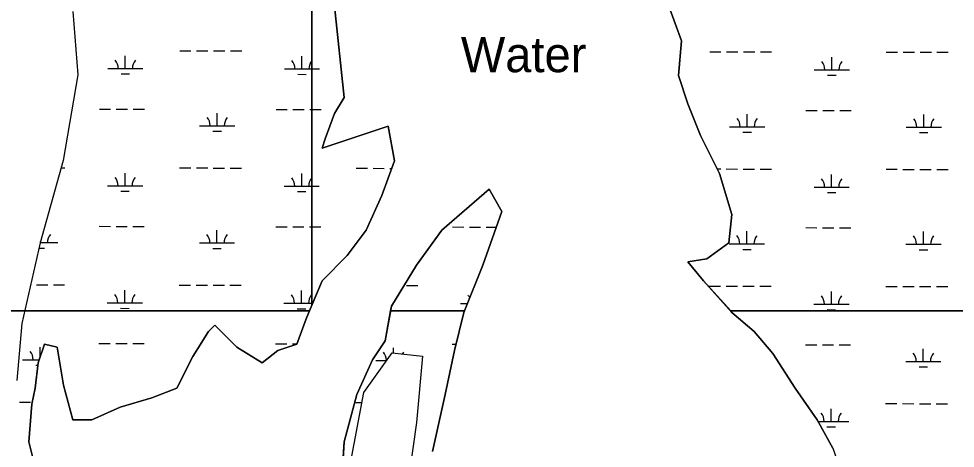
# Model space of a CAD drawing. Extents: x 3192952 to 3230831, y 849296 to 874698.
# Drawn here: x 3197892 to 3200553, y 858613 to 859832 of the extents above; entities that cross this region are included whole.
import ezdxf

# ---------------------------------------------------------------- set-up
doc = ezdxf.new("R2010")
doc.units = 0
for name, color, linetype in [('V-RIVR-IDEN', 7, 'Continuous'), ('V-SITE-VEGE', 7, 'Continuous'), ('V-TOPO-SHOR', 7, 'Continuous'), ('V-WETL-SWMP', 7, 'Continuous')]:
    doc.layers.add(name, color=color, linetype=linetype)

msp = doc.modelspace()

# ---------------------------------------------------------------- linework, layer by layer
at = {"layer": 'V-SITE-VEGE'}
for p, q in [((3198816.5, 859607.9), (3198789.6, 859868)), ((3199739.4, 859868), (3199775.3, 859769.3)), ((3199775.3, 859769.3), (3199766.3, 859670.7)), ((3199766.3, 859670.7), (3199793.2, 859590)), ((3198789.6, 859563.1), (3198816.5, 859607.9)), ((3199793.2, 859590), (3199829, 859500.3)), ((3198762.7, 859491.3), (3198789.6, 859563.1)), ((3198941.9, 859527.2), (3198753.8, 859464.4)), ((3198959.9, 859428.6), (3198941.9, 859527.2)), ((3198753.8, 859464.4), (3198762.7, 859491.3)), ((3199829, 859500.3), (3199882.8, 859392.7)), ((3198924, 859329.9), (3198959.9, 859428.6)), ((3199882.8, 859392.7), (3199918.6, 859276.1)), ((3198879.2, 859231.3), (3198924, 859329.9)), ((3199918.6, 859276.1), (3199909.7, 859195.4)), ((3198825.5, 859159.5), (3198879.2, 859231.3)), ((3199909.7, 859195.4), (3199847, 859150.6)), ((3198753.8, 859087.8), (3198825.5, 859159.5)), ((3199847, 859150.6), (3199793.2, 859141.6)), ((3199793.2, 859141.6), (3199838, 859087.8)), ((3198718.1, 859002.2), (3198753.8, 859087.8)), ((3199838, 859087.8), (3199915, 859002.2)), ((3197154.3, 859002.2), (3198718.1, 859002.2)), ((3198718.1, 859002.2), (3197154.3, 859002.2)), ((3198682.1, 858908.4), (3198709, 858980.2)), ((3198709, 858980.2), (3198718.1, 859002.2)), ((3198948.4, 859002.2), (3198933, 858917.4)), ((3199158.6, 859002.2), (3198948.4, 859002.2)), ((3199130.1, 858890.5), (3199157, 858998.1)), ((3199157, 858998.1), (3199158.6, 859002.2)), ((3199915, 859002.2), (3201858.8, 859002.2)), ((3201858.8, 859002.2), (3199915, 859002.2)), ((3199915, 859002.2), (3199918.6, 858998.1)), ((3199918.6, 858998.1), (3199981.4, 858944.3)), ((3198431.2, 858944.3), (3198449.1, 858962.2)), ((3198449.1, 858962.2), (3198511.8, 858899.5)), ((3198386.4, 858872.6), (3198431.2, 858944.3)), ((3199981.4, 858944.3), (3200035.1, 858881.5)), ((3197947.3, 858854.6), (3197965.2, 858908.4)), ((3197965.2, 858908.4), (3198001.1, 858899.5)), ((3198001.1, 858899.5), (3198019, 858791.9)), ((3198511.8, 858899.5), (3198583.5, 858854.6)), ((3198628.3, 858890.5), (3198682.1, 858908.4)), ((3198933, 858917.4), (3198897.1, 858863.6)), ((3198341.6, 858782.9), (3198386.4, 858872.6)), ((3198583.5, 858854.6), (3198628.3, 858890.5)), ((3199103.2, 858765), (3199130.1, 858890.5)), ((3200035.1, 858881.5), (3200097.9, 858782.9)), ((3197938.4, 858782.9), (3197947.3, 858854.6)), ((3198897.1, 858863.6), (3198852.3, 858765)), ((3197929.4, 858738.1), (3197938.4, 858782.9)), ((3198019, 858791.9), (3198045.9, 858693.2)), ((3198269.9, 858756), (3198341.6, 858782.9)), ((3200097.9, 858782.9), (3200160.6, 858693.2)), ((3198180.3, 858729.1), (3198269.9, 858756)), ((3198852.3, 858765), (3198816.5, 858630.4)), ((3199067.4, 858603.5), (3199103.2, 858765)), ((3197920.4, 858630.4), (3197929.4, 858738.1)), ((3198099.6, 858693.2), (3198180.3, 858729.1)), ((3198045.9, 858693.2), (3198099.6, 858693.2)), ((3200160.6, 858693.2), (3200205.4, 858612.5)), ((3197938.4, 858558.7), (3197920.4, 858630.4)), ((3198816.5, 858630.4), (3198807.5, 858487))]:
    msp.add_line(p, q, dxfattribs=at)
msp.add_lwpolyline([(3198948.4, 859002.2), (3199158.6, 859002.2), (3199210.8, 859132.6), (3199264.5, 859285.1), (3199228.7, 859347.8), (3199094.3, 859231.3), (3199022.6, 859132.6), (3198950.9, 859016)], close=True, dxfattribs=at)
at = {"layer": 'V-TOPO-SHOR'}
for points in [[(3198789.6, 859868), (3198816.5, 859607.9), (3198789.6, 859563.1), (3198762.7, 859491.3), (3198753.8, 859464.4), (3198941.9, 859527.2), (3198959.9, 859428.6), (3198924, 859329.9), (3198879.2, 859231.3), (3198825.5, 859159.5), (3198753.8, 859087.8), (3198718.1, 859002.2), (3198709, 858980.2), (3198682.1, 858908.4), (3198628.3, 858890.5), (3198583.5, 858854.6), (3198511.8, 858899.5), (3198449.1, 858962.2), (3198431.2, 858944.3), (3198386.4, 858872.6), (3198341.6, 858782.9), (3198269.9, 858756), (3198180.3, 858729.1), (3198099.6, 858693.2), (3198045.9, 858693.2), (3198019, 858791.9), (3198001.1, 858899.5), (3197965.2, 858908.4), (3197947.3, 858854.6), (3197938.4, 858782.9), (3197929.4, 858738.1), (3197920.4, 858630.4), (3197938.4, 858558.7)], [(3200205.4, 858612.5), (3200160.6, 858693.2), (3200097.9, 858782.9), (3200035.1, 858881.5), (3199981.4, 858944.3), (3199918.6, 858998.1), (3199915, 859002.2), (3199838, 859087.8), (3199793.2, 859141.6), (3199847, 859150.6), (3199909.7, 859195.4), (3199918.6, 859276.1), (3199882.8, 859392.7), (3199829, 859500.3), (3199793.2, 859590), (3199766.3, 859670.7), (3199775.3, 859769.3), (3199739.4, 859868)], [(3198948.4, 859002.2), (3198950.9, 859016), (3199022.6, 859132.6), (3199094.3, 859231.3), (3199228.7, 859347.8), (3199264.5, 859285.1), (3199210.8, 859132.6), (3199158.6, 859002.2), (3199157, 858998.1), (3199130.1, 858890.5), (3199103.2, 858765), (3199067.4, 858603.5)], [(3198807.5, 858487), (3198816.5, 858630.4), (3198852.3, 858765), (3198897.1, 858863.6), (3198933, 858917.4), (3198948.4, 859002.2)]]:
    msp.add_lwpolyline(points, dxfattribs=at)
at = {"layer": 'V-WETL-SWMP'}
for p, q in [((3198724.9, 859018.4), (3198724.9, 860563.9)), ((3199739.4, 859868), (3199775.3, 859769.3)), ((3198045.4, 859852.3), (3198060.1, 859672.9)), ((3199775.3, 859769.3), (3199766.3, 859670.7)), ((3198194.8, 859690.5), (3198194.8, 859726.5)), ((3198349.4, 859741), (3198381.4, 859740.9)), ((3198397.4, 859740.9), (3198429.4, 859740.8)), ((3198445.4, 859740.8), (3198477.4, 859740.7)), ((3198493.4, 859740.7), (3198525.4, 859740.7)), ((3198696.7, 859689.6), (3198696.7, 859725.6)), ((3199855.2, 859738.1), (3199887.2, 859738.1)), ((3199903.2, 859738), (3199935.2, 859738)), ((3199951.2, 859738), (3199983.2, 859737.9)), ((3199999.2, 859737.9), (3200031.2, 859737.8)), ((3200357.1, 859737.2), (3200389.1, 859737.1)), ((3200405.1, 859737.1), (3200437.1, 859737)), ((3200453.1, 859737), (3200485.1, 859736.9)), ((3200501.1, 859736.9), (3200533.1, 859736.9)), ((3200202.4, 859686.7), (3200202.5, 859722.7)), ((3198060.1, 859672.9), (3198018.6, 859429.9)), ((3198144.8, 859690.6), (3198244.8, 859690.4)), ((3198182.7, 859675.1), (3198206.7, 859675.1)), ((3198646.7, 859689.7), (3198724.9, 859689.5)), ((3198684.6, 859674.2), (3198708.6, 859674.1)), ((3198724.9, 859689.5), (3198746.7, 859689.5)), ((3199766.3, 859670.7), (3199793.2, 859590)), ((3200152.4, 859686.8), (3200252.4, 859686.6)), ((3200190.4, 859671.3), (3200214.4, 859671.3)), ((3198121.1, 859575.2), (3198153.1, 859575.2)), ((3198169.1, 859575.1), (3198201.1, 859575.1)), ((3198217.1, 859575.1), (3198249.1, 859575)), ((3198455.9, 859528.2), (3198456, 859564.2)), ((3198623, 859574.3), (3198655, 859574.2)), ((3198671, 859574.2), (3198703, 859574.1)), ((3198719, 859574.1), (3198724.9, 859574.1)), ((3198724.9, 859574.1), (3198751, 859574)), ((3199793.2, 859590), (3199829, 859500.3)), ((3200128.8, 859571.4), (3200160.8, 859571.4)), ((3200176.8, 859571.4), (3200208.8, 859571.3)), ((3200224.8, 859571.3), (3200256.8, 859571.2)), ((3199961.6, 859525.3), (3199961.7, 859561.3)), ((3200463.5, 859524.4), (3200463.6, 859560.4)), ((3198405.9, 859528.3), (3198505.9, 859528.1)), ((3198443.9, 859512.8), (3198467.9, 859512.7)), ((3199911.6, 859525.4), (3200011.6, 859525.2)), ((3200413.5, 859524.5), (3200513.5, 859524.3)), ((3199829, 859500.3), (3199882.8, 859392.7)), ((3199949.6, 859509.9), (3199973.6, 859509.9)), ((3200451.5, 859509), (3200475.5, 859508.9)), ((3198018.6, 859429.9), (3197952.4, 859195.7)), ((3198012.6, 859408.9), (3198022.9, 859408.9)), ((3198348.8, 859408.3), (3198380.8, 859408.2)), ((3198396.8, 859408.2), (3198428.8, 859408.2)), ((3198444.8, 859408.1), (3198476.8, 859408.1)), ((3198492.8, 859408), (3198524.8, 859408)), ((3198850.7, 859407.4), (3198882.7, 859407.3)), ((3198898.7, 859407.3), (3198930.7, 859407.2)), ((3198946.7, 859407.2), (3198952.1, 859407.2)), ((3199876.4, 859405.4), (3199886.5, 859405.4)), ((3199902.5, 859405.4), (3199934.5, 859405.3)), ((3199950.5, 859405.3), (3199982.5, 859405.2)), ((3199998.5, 859405.2), (3200030.5, 859405.1)), ((3200356.4, 859404.5), (3200388.4, 859404.5)), ((3200404.4, 859404.4), (3200436.4, 859404.4)), ((3198194.1, 859357.9), (3198194.2, 859393.9)), ((3198696, 859356.9), (3198696.1, 859392.9)), ((3199882.8, 859392.7), (3199918.6, 859276.1)), ((3200201.8, 859354.1), (3200201.8, 859390.1)), ((3200452.4, 859404.3), (3200484.4, 859404.3)), ((3200500.4, 859404.2), (3200532.4, 859404.2)), ((3198144.1, 859358), (3198244.1, 859357.8)), ((3198646, 859357), (3198724.9, 859356.9)), ((3198724.9, 859356.9), (3198746, 859356.8)), ((3200151.8, 859354.2), (3200251.8, 859354)), ((3198182.1, 859342.5), (3198206.1, 859342.4)), ((3198684, 859341.5), (3198708, 859341.5)), ((3199228.7, 859347.9), (3199094.3, 859231.3)), ((3199264.5, 859285.1), (3199228.7, 859347.9)), ((3200189.7, 859338.7), (3200213.7, 859338.6)), ((3199210.8, 859132.6), (3199264.5, 859285.1)), ((3199918.6, 859276.1), (3199909.7, 859195.4)), ((3198120.5, 859242.6), (3198152.5, 859242.5)), ((3198168.5, 859242.5), (3198200.5, 859242.4)), ((3198216.5, 859242.4), (3198248.5, 859242.3)), ((3198455.3, 859195.5), (3198455.3, 859231.5)), ((3198622.4, 859241.6), (3198654.4, 859241.6)), ((3198670.4, 859241.5), (3198702.4, 859241.5)), ((3198718.4, 859241.4), (3198724.9, 859241.4)), ((3198724.9, 859241.4), (3198750.4, 859241.4)), ((3199094.3, 859231.3), (3199022.6, 859132.6)), ((3199124.3, 859240.7), (3199156.3, 859240.6)), ((3199172.3, 859240.6), (3199204.3, 859240.5)), ((3199220.3, 859240.5), (3199248.8, 859240.4)), ((3199961, 859192.7), (3199961, 859228.7)), ((3200128.1, 859238.8), (3200160.1, 859238.7)), ((3200176.1, 859238.7), (3200208.1, 859238.6)), ((3200224.1, 859238.6), (3200256.1, 859238.5)), ((3200462.9, 859191.7), (3200463, 859227.7)), ((3197952.4, 859195.7), (3197900.3, 858966.8)), ((3197952.6, 859196.5), (3198003.4, 859196.4)), ((3197953.4, 859196.5), (3197953.4, 859199.1)), ((3198405.3, 859195.6), (3198505.3, 859195.4)), ((3199909.7, 859195.4), (3199847, 859150.6)), ((3199911, 859192.8), (3200011, 859192.6)), ((3200412.9, 859191.8), (3200512.9, 859191.6)), ((3197949.1, 859181), (3197965.3, 859181)), ((3198443.2, 859180.1), (3198467.2, 859180)), ((3199949, 859177.2), (3199973, 859177.2)), ((3200450.9, 859176.3), (3200474.9, 859176.3)), ((3199847, 859150.6), (3199793.2, 859141.6)), ((3199793.2, 859141.6), (3199838, 859087.8)), ((3199022.6, 859132.6), (3198950.9, 859016.1)), ((3199157, 858998.1), (3199210.8, 859132.6)), ((3199838, 859087.8), (3199918.6, 858998.1)), ((3197925.3, 859076.4), (3197926.3, 859076.4)), ((3197942.3, 859076.4), (3197974.3, 859076.3)), ((3197990.3, 859076.3), (3198022.3, 859076.3)), ((3198193.5, 859025.2), (3198193.6, 859061.2)), ((3198348.2, 859075.6), (3198380.2, 859075.6)), ((3198396.2, 859075.5), (3198428.2, 859075.5)), ((3198444.2, 859075.5), (3198476.2, 859075.4)), ((3198492.2, 859075.4), (3198524.2, 859075.3)), ((3198695.4, 859024.2), (3198695.5, 859060.2)), ((3198994.1, 859074.4), (3199026.1, 859074.4)), ((3199853.9, 859072.8), (3199885.9, 859072.7)), ((3199901.9, 859072.7), (3199933.9, 859072.6)), ((3199949.9, 859072.6), (3199981.9, 859072.5)), ((3199997.9, 859072.5), (3200029.9, 859072.5)), ((3200355.8, 859071.8), (3200387.8, 859071.8)), ((3200403.8, 859071.7), (3200435.8, 859071.7)), ((3200451.8, 859071.7), (3200483.8, 859071.6)), ((3200499.8, 859071.6), (3200531.8, 859071.5)), ((3200201.1, 859021.4), (3200201.2, 859057.4)), ((3198143.5, 859025.3), (3198243.5, 859025.1)), ((3198181.5, 859009.8), (3198205.5, 859009.7)), ((3198645.4, 859024.3), (3198724.9, 859024.2)), ((3198683.4, 859008.8), (3198707.4, 859008.8)), ((3198709, 858980.2), (3198724.9, 859018.4)), ((3198724.9, 859024.2), (3198727.3, 859024.2)), ((3198950.9, 859016.1), (3198933, 858917.4)), ((3199147.3, 859023.4), (3199167.1, 859023.3)), ((3200151.1, 859021.5), (3200251.1, 859021.3)), ((3200189.1, 859006), (3200213.1, 859005.9)), ((3198682.1, 858908.4), (3198709, 858980.2)), ((3199130.1, 858890.5), (3199157, 858998.1)), ((3199918.6, 858998.1), (3199981.4, 858944.3)), ((3197900.3, 858966.8), (3197886.7, 858804.9)), ((3198431.2, 858944.3), (3198449.1, 858962.2)), ((3198449.1, 858962.2), (3198511.8, 858899.5)), ((3198386.4, 858872.6), (3198431.2, 858944.3)), ((3199981.4, 858944.3), (3200035.1, 858881.5)), ((3197947.3, 858854.6), (3197965.2, 858908.4)), ((3197952.7, 858870.9), (3197952.8, 858899.8)), ((3197965.2, 858908.4), (3198001.1, 858899.5)), ((3198001.1, 858899.5), (3198019, 858791.9)), ((3198119.9, 858909.9), (3198151.9, 858909.8)), ((3198167.9, 858909.8), (3198199.9, 858909.7)), ((3198215.9, 858909.7), (3198247.9, 858909.6)), ((3198511.8, 858899.5), (3198583.5, 858854.6)), ((3198621.8, 858908.9), (3198653.8, 858908.9)), ((3198628.3, 858890.5), (3198682.1, 858908.4)), ((3198669.8, 858908.9), (3198682.2, 858908.8)), ((3198933, 858917.4), (3198897.1, 858863.6)), ((3199123.7, 858908), (3199134.5, 858908)), ((3200127.5, 858906.1), (3200159.5, 858906)), ((3200175.5, 858906), (3200207.5, 858905.9)), ((3200223.5, 858905.9), (3200255.5, 858905.9)), ((3198341.6, 858782.9), (3198386.4, 858872.6)), ((3198583.5, 858854.6), (3198628.3, 858890.5)), ((3198872.1, 858770.9), (3198952.7, 858883.8)), ((3198952.7, 858883.8), (3199039, 858873.5)), ((3198956.6, 858883.3), (3198956.6, 858897.9)), ((3199039, 858873.5), (3199022, 858685.2)), ((3199103.2, 858765), (3199130.1, 858890.5)), ((3200035.1, 858881.5), (3200097.8, 858782.9)), ((3200462.3, 858859), (3200462.3, 858895)), ((3197902.7, 858863.9), (3197950.4, 858863.8)), ((3197938.4, 858782.9), (3197947.3, 858854.6)), ((3197940.7, 858848.4), (3197946.5, 858848.4)), ((3198897.1, 858863.6), (3198852.3, 858765)), ((3198906.5, 858862), (3198937.1, 858861.9)), ((3200412.3, 858859.1), (3200512.3, 858858.9)), ((3200450.2, 858843.6), (3200474.2, 858843.6)), ((3197929.4, 858738.1), (3197938.4, 858782.9)), ((3198019, 858791.9), (3198045.9, 858693.2)), ((3198269.9, 858756), (3198341.6, 858782.9)), ((3198832.3, 858559.7), (3198872.1, 858770.9)), ((3200097.8, 858782.9), (3200160.6, 858693.2)), ((3197893.7, 858743.8), (3197925.7, 858743.8)), ((3198180.3, 858729.1), (3198269.9, 858756)), ((3198852.3, 858765), (3198816.5, 858630.4)), ((3198849.5, 858742), (3198866.7, 858742)), ((3199067.4, 858603.5), (3199103.2, 858765)), ((3200355.2, 858739.2), (3200387.2, 858739.1)), ((3197920.4, 858630.4), (3197929.4, 858738.1)), ((3198099.6, 858693.2), (3198180.3, 858729.1)), ((3200200.5, 858688.7), (3200200.6, 858724.7)), ((3200403.2, 858739.1), (3200435.2, 858739)), ((3200451.2, 858739), (3200483.2, 858738.9)), ((3200499.2, 858738.9), (3200531.2, 858738.8)), ((3198045.9, 858693.2), (3198099.6, 858693.2)), ((3200160.6, 858693.2), (3200205.4, 858612.5)), ((3200163, 858688.8), (3200250.5, 858688.6)), ((3199022, 858685.2), (3198991, 858461.6)), ((3200188.5, 858673.3), (3200212.5, 858673.3)), ((3197938.4, 858558.7), (3197920.4, 858630.4)), ((3198816.5, 858630.4), (3198807.5, 858487)), ((3200205.4, 858612.5), (3200250.2, 858487))]:
    msp.add_line(p, q, dxfattribs=at)
msp.add_lwpolyline([(3198724.9, 860563.9), (3198724.9, 859018.4), (3198753.8, 859087.8), (3198825.5, 859159.5), (3198879.2, 859231.3), (3198924, 859329.9), (3198959.9, 859428.6), (3198941.9, 859527.2), (3198753.8, 859464.4), (3198762.7, 859491.3), (3198789.6, 859563.1), (3198816.5, 859607.9), (3198789.6, 859868)], dxfattribs=at)
for centre, start, end in [((3198139.5, 859691.1), 359.1198, 40.6635), ((3198250, 859690.9), 139.1198, 180.6635), ((3198641.4, 859690.2), 359.1198, 40.6635), ((3198751.9, 859690), 140.0391, 180.6635), ((3198751.9, 859690), 139.1198, 140.0388), ((3200147.1, 859687.3), 359.1198, 40.6635), ((3200257.6, 859687.1), 139.1198, 180.6635), ((3198400.6, 859528.8), 359.1198, 40.6635), ((3198511.1, 859528.5), 139.1198, 180.6635), ((3199906.4, 859525.9), 359.1198, 40.6635), ((3200016.9, 859525.7), 139.1198, 180.6635), ((3200408.3, 859525), 359.1198, 40.6635), ((3200518.8, 859524.8), 139.1198, 180.6635), ((3198138.9, 859358.4), 359.1198, 40.6635), ((3198249.4, 859358.2), 139.1198, 180.6635), ((3198640.8, 859357.5), 359.1198, 40.6635), ((3198751.3, 859357.3), 139.1198, 180.6635), ((3200146.5, 859354.6), 359.1198, 40.6635), ((3200257, 859354.4), 139.1198, 180.6635), ((3198008.6, 859196.8), 139.1198, 180.6635), ((3198400, 859196.1), 359.1198, 40.6635), ((3198510.5, 859195.9), 139.1198, 180.6635), ((3199905.7, 859193.2), 359.1198, 40.6635), ((3200016.2, 859193), 139.1198, 180.6635), ((3200407.6, 859192.3), 359.1198, 40.6635), ((3200518.1, 859192.1), 139.1198, 180.6635), ((3198138.3, 859025.8), 359.1198, 40.6635), ((3198248.7, 859025.6), 139.1198, 180.6635), ((3198640.2, 859024.8), 359.1198, 40.6635), ((3198750.7, 859024.6), 139.1198, 180.6635), ((3199142.1, 859023.9), 26.6015, 40.6635), ((3200145.9, 859022), 359.1198, 40.6635), ((3200256.4, 859021.8), 139.1198, 180.6635), ((3197897.5, 858864.4), 359.1198, 40.6635), ((3198901.3, 858862.5), 359.1198, 40.6635), ((3199011.8, 858862.3), 139.1198, 149.134), ((3200407, 858859.6), 359.1198, 40.6635), ((3200517.5, 858859.4), 139.1198, 180.6635), ((3200145.3, 858689.3), 359.1198, 40.6635), ((3200255.7, 858689.1), 139.1198, 180.6635)]:
    msp.add_arc(centre, 35.2, start, end, dxfattribs=at)

# ---------------------------------------------------------------- texts
at = {"layer": 'V-RIVR-IDEN'}
msp.add_text('Water', height=100, dxfattribs=at).set_placement((3199148.2, 859680.2))

doc.saveas('drawing.dxf')
